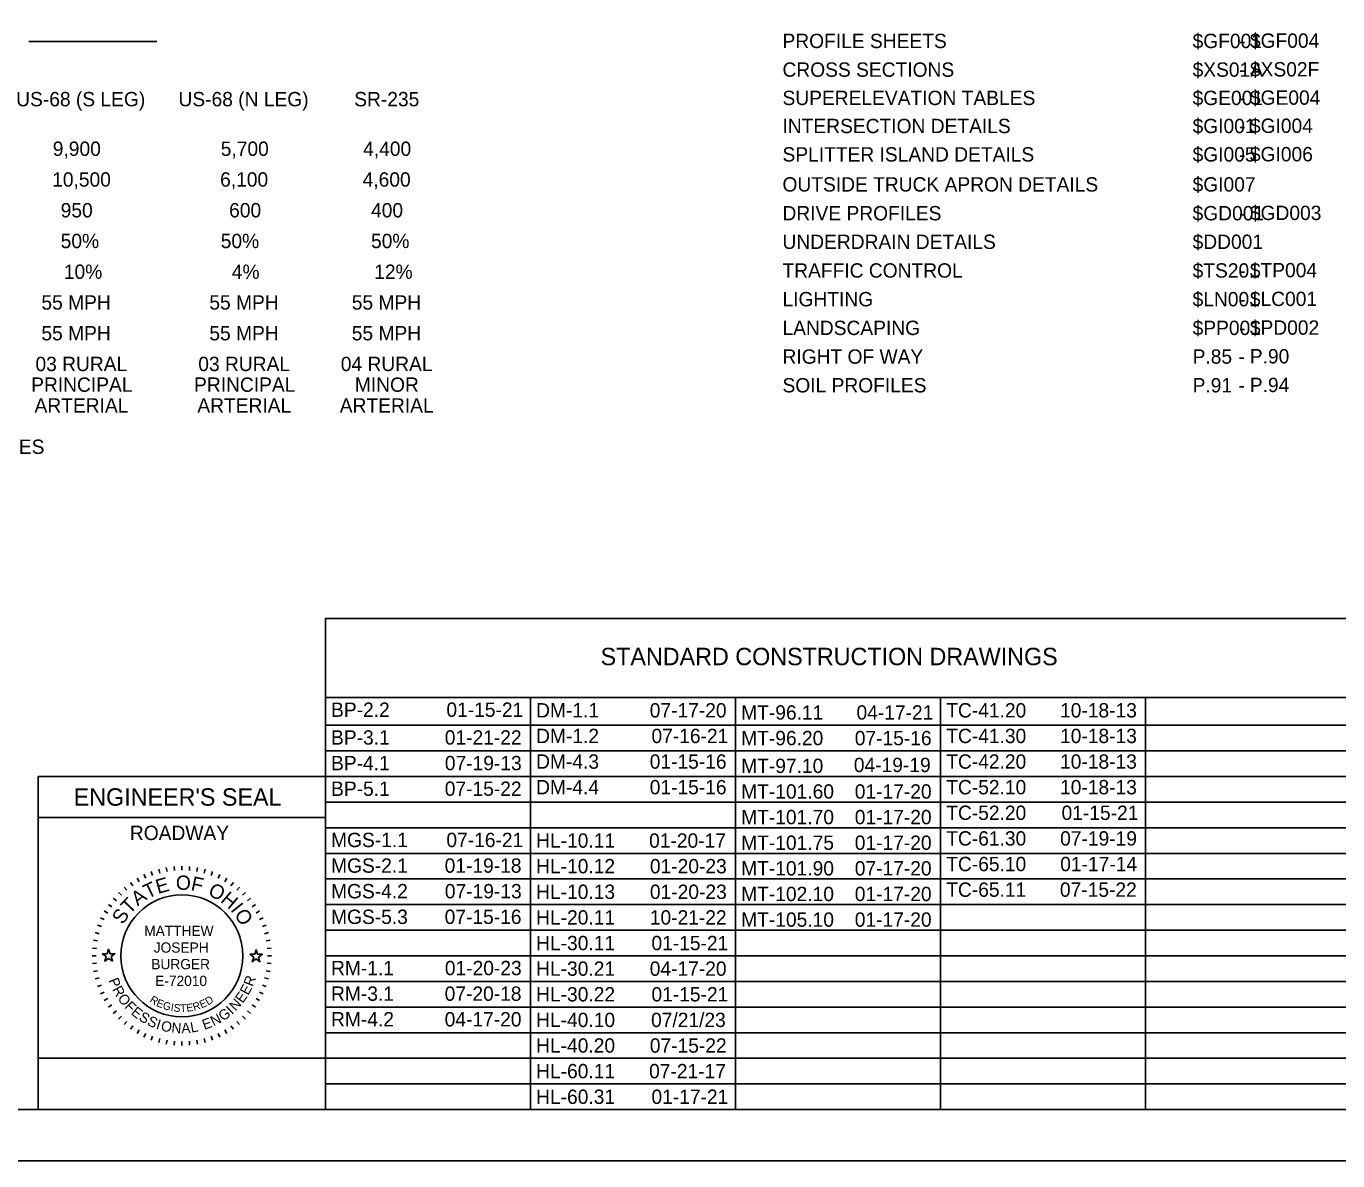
# Model space of a CAD drawing. Extents: x 39.5 to 73.5, y 15.6 to 37.6.
# Drawn here: x 47.83 to 60.62, y 15.6 to 26.67 of the extents above; entities that cross this region are included whole.
import ezdxf

# ---------------------------------------------------------------- set-up
doc = ezdxf.new("R2010")
doc.units = 0
for name, color, linetype in [('GM_X_City_Street', 7, 'Continuous'), ('GM_X_Hydro_Text', 7, 'Continuous'), ('GM_X_Interstate_Route', 7, 'Continuous'), ('GM_X_Major_River_Text', 7, 'Continuous')]:
    doc.layers.add(name, color=color, linetype=linetype)

msp = doc.modelspace()

# ---------------------------------------------------------------- linework, layer by layer
at = {"layer": 'GM_X_City_Street'}
msp.add_lwpolyline([(41.501, 37.101), (73.001, 37.101), (73.001, 16.101), (41.501, 16.101)], close=True, dxfattribs=at)
at = {"layer": 'GM_X_Hydro_Text'}
msp.add_lwpolyline([(39.501, 15.601), (73.501, 15.601), (73.501, 37.601), (39.501, 37.601)], close=True, dxfattribs=at)
at = {"layer": 'GM_X_Major_River_Text'}
for p, q in [((49.108, 26.523), (47.858, 26.523)), ((50.751, 20.893), (64.201, 20.893)), ((50.751, 16.101), (50.751, 20.893)), ((50.751, 20.122), (64.201, 20.122)), ((52.751, 16.101), (52.751, 20.122)), ((54.751, 16.101), (54.751, 20.122)), ((56.751, 16.101), (56.751, 20.122)), ((58.751, 16.101), (58.751, 20.122)), ((50.751, 19.851), (64.201, 19.851)), ((50.751, 19.601), (64.201, 19.601)), ((50.751, 19.351), (47.951, 19.351)), ((47.951, 19.351), (47.951, 16.101)), ((50.751, 19.351), (64.201, 19.351)), ((50.751, 16.101), (50.751, 19.351)), ((50.751, 19.101), (64.201, 19.101)), ((50.751, 18.951), (47.951, 18.951)), ((50.751, 18.851), (64.201, 18.851)), ((50.751, 18.601), (64.201, 18.601)), ((49.052, 18.423), (49.066, 18.386)), ((49.125, 18.446), (49.135, 18.408)), ((49.199, 18.463), (49.206, 18.423)), ((49.275, 18.473), (49.278, 18.433)), ((49.351, 18.476), (49.351, 18.436)), ((49.427, 18.473), (49.424, 18.433)), ((49.503, 18.463), (49.496, 18.423)), ((49.578, 18.446), (49.567, 18.408)), ((49.65, 18.423), (49.637, 18.386)), ((48.849, 18.318), (48.872, 18.285)), ((48.914, 18.359), (48.934, 18.324)), ((48.981, 18.394), (48.998, 18.358)), ((49.721, 18.394), (49.704, 18.358)), ((49.789, 18.359), (49.769, 18.324)), ((49.853, 18.318), (49.83, 18.285)), ((50.751, 18.351), (64.201, 18.351)), ((48.732, 18.22), (48.761, 18.192)), ((48.789, 18.271), (48.814, 18.241)), ((49.914, 18.271), (49.888, 18.241)), ((49.97, 18.22), (49.942, 18.192)), ((48.593, 18.039), (48.628, 18.019)), ((48.634, 18.103), (48.667, 18.08)), ((48.681, 18.164), (48.712, 18.138)), ((50.021, 18.164), (49.991, 18.138)), ((50.068, 18.103), (50.035, 18.08)), ((50.109, 18.039), (50.074, 18.019)), ((50.751, 18.101), (64.201, 18.101)), ((48.558, 17.971), (48.594, 17.954)), ((50.144, 17.971), (50.108, 17.954)), ((48.506, 17.828), (48.545, 17.817)), ((48.529, 17.9), (48.567, 17.887)), ((50.173, 17.9), (50.136, 17.887)), ((50.196, 17.828), (50.158, 17.817)), ((50.751, 17.851), (64.201, 17.851)), ((48.48, 17.677), (48.519, 17.674)), ((48.49, 17.753), (48.529, 17.746)), ((50.213, 17.753), (50.174, 17.746)), ((50.223, 17.677), (50.183, 17.674)), ((48.476, 17.601), (48.516, 17.601)), ((48.48, 17.525), (48.519, 17.528)), ((50.223, 17.525), (50.183, 17.528)), ((50.226, 17.601), (50.186, 17.601)), ((50.751, 17.601), (64.201, 17.601)), ((48.49, 17.449), (48.529, 17.456)), ((50.213, 17.449), (50.174, 17.456)), ((48.506, 17.375), (48.545, 17.385)), ((48.529, 17.302), (48.567, 17.315)), ((50.173, 17.302), (50.136, 17.315)), ((50.196, 17.375), (50.158, 17.385)), ((50.751, 17.351), (64.201, 17.351)), ((48.558, 17.231), (48.594, 17.248)), ((48.593, 17.164), (48.628, 17.184)), ((50.109, 17.164), (50.074, 17.184)), ((50.144, 17.231), (50.108, 17.248)), ((48.634, 17.099), (48.667, 17.122)), ((48.681, 17.039), (48.712, 17.064)), ((50.021, 17.039), (49.991, 17.064)), ((50.068, 17.099), (50.035, 17.122)), ((50.751, 17.101), (64.201, 17.101)), ((48.732, 16.982), (48.761, 17.011)), ((48.789, 16.931), (48.814, 16.961)), ((48.849, 16.884), (48.872, 16.917)), ((49.853, 16.884), (49.83, 16.917)), ((49.914, 16.931), (49.888, 16.961)), ((49.97, 16.982), (49.942, 17.011)), ((48.914, 16.843), (48.934, 16.878)), ((48.981, 16.808), (48.998, 16.844)), ((49.052, 16.779), (49.066, 16.816)), ((49.125, 16.756), (49.135, 16.795)), ((49.199, 16.739), (49.206, 16.779)), ((49.275, 16.729), (49.278, 16.769)), ((49.351, 16.726), (49.351, 16.766)), ((49.427, 16.729), (49.424, 16.769)), ((49.503, 16.739), (49.496, 16.779)), ((49.578, 16.756), (49.567, 16.795)), ((49.65, 16.779), (49.637, 16.816)), ((49.721, 16.808), (49.704, 16.844)), ((49.789, 16.843), (49.769, 16.878)), ((50.751, 16.851), (64.201, 16.851)), ((50.751, 16.601), (64.201, 16.601)), ((50.751, 16.351), (64.201, 16.351)), ((50.751, 16.101), (47.951, 16.101))]:
    msp.add_line(p, q, dxfattribs=at)
for points in [[(48.575, 17.621), (48.622, 17.621), (48.636, 17.666), (48.651, 17.621), (48.698, 17.621), (48.66, 17.593), (48.674, 17.549), (48.636, 17.576), (48.598, 17.549), (48.613, 17.593)], [(50.014, 17.616), (50.061, 17.616), (50.075, 17.66), (50.09, 17.616), (50.137, 17.616), (50.099, 17.588), (50.113, 17.543), (50.075, 17.571), (50.037, 17.543), (50.052, 17.588)], [(50.751, 16.101), (50.751, 16.601), (47.951, 16.601), (47.951, 16.101)]]:
    msp.add_lwpolyline(points, close=True, dxfattribs=at)
msp.add_circle((49.351, 17.601), 0.595, dxfattribs=at)

# ---------------------------------------------------------------- texts
at = {"layer": 'GM_X_Interstate_Route'}
for s, height, p in [('$GF001', 0.14, (59.209, 26.459)), ('$GF004', 0.14, (59.768, 26.462)), ('PROFILE SHEETS', 0.14, (55.209, 26.459)), ('-', 0.14, (59.664, 26.459)), ('CROSS SECTIONS', 0.14, (55.209, 26.179)), ('$XS01A', 0.14, (59.209, 26.179)), ('-', 0.14, (59.664, 26.179)), ('$XS02F', 0.14, (59.768, 26.182)), ('US-68 (S LEG)', 0.14, (47.735, 25.891)), ('US-68 (N LEG)', 0.14, (49.318, 25.891)), ('SR-235', 0.14, (51.032, 25.891)), ('SUPERELEVATION TABLES', 0.14, (55.209, 25.903)), ('$GE001', 0.14, (59.209, 25.903)), ('$GE004', 0.14, (59.768, 25.906)), ('-', 0.14, (59.664, 25.903)), ('INTERSECTION DETAILS', 0.14, (55.209, 25.629)), ('$GI001', 0.14, (59.209, 25.629)), ('$GI004', 0.14, (59.768, 25.631)), ('-', 0.14, (59.664, 25.629)), ('9,900', 0.14, (48.092, 25.407)), ('5,700', 0.14, (49.73, 25.407)), ('4,400', 0.14, (51.119, 25.407)), ('SPLITTER ISLAND DETAILS', 0.14, (55.209, 25.352)), ('$GI005', 0.14, (59.209, 25.352)), ('$GI006', 0.14, (59.768, 25.354)), ('-', 0.14, (59.664, 25.351)), ('10,500', 0.14, (48.086, 25.107)), ('6,100', 0.14, (49.724, 25.107)), ('4,600', 0.14, (51.114, 25.107)), ('OUTSIDE TRUCK APRON DETAILS', 0.14, (55.209, 25.059)), ('$GI007', 0.14, (59.209, 25.059)), ('950', 0.14, (48.169, 24.807)), ('600', 0.14, (49.812, 24.807)), ('400', 0.14, (51.196, 24.807)), ('DRIVE PROFILES', 0.14, (55.209, 24.778)), ('$GD001', 0.14, (59.209, 24.778)), ('-', 0.14, (59.664, 24.778)), ('$GD003', 0.14, (59.768, 24.781)), ('50%', 0.14, (48.169, 24.507)), ('50%', 0.14, (49.73, 24.507)), ('50%', 0.14, (51.196, 24.507)), ('UNDERDRAIN DETAILS', 0.14, (55.209, 24.499)), ('$DD001', 0.14, (59.209, 24.499)), ('10%', 0.14, (48.2, 24.207)), ('4%', 0.14, (49.838, 24.207)), ('12%', 0.14, (51.227, 24.207)), ('TRAFFIC CONTROL', 0.14, (55.209, 24.219)), ('$TS201', 0.14, (59.209, 24.219)), ('$TP004', 0.14, (59.767, 24.222)), ('-', 0.14, (59.664, 24.219)), ('LIGHTING ', 0.14, (55.209, 23.939)), ('$LN001', 0.14, (59.209, 23.939)), ('$LC001', 0.14, (59.767, 23.942)), ('55 MPH', 0.14, (47.981, 23.907)), ('55 MPH', 0.14, (49.619, 23.907)), ('55 MPH', 0.14, (51.008, 23.907)), ('-', 0.14, (59.664, 23.939)), ('LANDSCAPING', 0.14, (55.209, 23.659)), ('$PP001', 0.14, (59.209, 23.659)), ('$PD002', 0.14, (59.767, 23.662)), ('55 MPH', 0.14, (47.981, 23.607)), ('55 MPH', 0.14, (49.619, 23.607)), ('55 MPH', 0.14, (51.008, 23.607)), ('-', 0.14, (59.664, 23.659)), ('03 RURAL', 0.14, (47.923, 23.307)), ('03 RURAL', 0.14, (49.511, 23.307)), ('04 RURAL', 0.14, (50.901, 23.307)), ('RIGHT OF WAY', 0.14, (55.209, 23.379)), ('P.85', 0.14, (59.209, 23.379)), ('-', 0.14, (59.655, 23.379)), ('P.90', 0.14, (59.767, 23.382)), ('PRINCIPAL', 0.14, (47.881, 23.105)), ('PRINCIPAL', 0.14, (49.47, 23.105)), ('MINOR', 0.14, (51.038, 23.105)), ('SOIL PROFILES', 0.14, (55.209, 23.099)), ('P.91', 0.14, (59.209, 23.099)), ('-', 0.14, (59.655, 23.099)), ('P.94', 0.14, (59.767, 23.102)), ('ARTERIAL', 0.14, (47.914, 22.902)), ('ARTERIAL', 0.14, (49.502, 22.902)), ('ARTERIAL', 0.14, (50.891, 22.902)), ('NHS PROJECT.................................................................................YES', 0.14, (42.102, 22.499)), ('STANDARD CONSTRUCTION DRAWINGS', 0.17, (53.435, 20.437)), ('BP-2.2', 0.14, (50.806, 19.933)), ('01-15-21', 0.14, (51.931, 19.933)), ('DM-1.1', 0.14, (52.806, 19.927)), ('07-17-20', 0.14, (53.914, 19.927)), ('MT-96.11', 0.14, (54.806, 19.906)), ('04-17-21', 0.14, (55.931, 19.906)), ('TC-41.20', 0.14, (56.806, 19.927)), ('10-18-13', 0.14, (57.916, 19.927)), ('BP-3.1', 0.14, (50.806, 19.662)), ('01-21-22', 0.14, (51.915, 19.662)), ('DM-1.2', 0.14, (52.806, 19.677)), ('07-16-21', 0.14, (53.931, 19.677)), ('MT-96.20', 0.14, (54.806, 19.656)), ('07-15-16', 0.14, (55.914, 19.656)), ('TC-41.30', 0.14, (56.806, 19.677)), ('10-18-13', 0.14, (57.916, 19.677)), ('BP-4.1', 0.14, (50.806, 19.412)), ('07-19-13', 0.14, (51.916, 19.412)), ('DM-4.3', 0.14, (52.806, 19.427)), ('01-15-16', 0.14, (53.914, 19.427)), ('MT-97.10', 0.14, (54.806, 19.385)), ('04-19-19', 0.14, (55.905, 19.394)), ('TC-42.20', 0.14, (56.806, 19.427)), ('10-18-13', 0.14, (57.916, 19.427)), ('DM-4.4', 0.14, (52.806, 19.177)), ('01-15-16', 0.14, (53.914, 19.177)), ('TC-52.10', 0.14, (56.806, 19.177)), ('10-18-13', 0.14, (57.916, 19.177)), ('BP-5.1', 0.14, (50.806, 19.162)), ('07-15-22', 0.14, (51.915, 19.162)), ('MT-101.60', 0.14, (54.806, 19.135)), ('01-17-20', 0.14, (55.914, 19.135)), ('TC-52.20', 0.14, (56.806, 18.927)), ('01-15-21', 0.14, (57.931, 18.927)), ('MT-101.70', 0.14, (54.806, 18.885)), ('01-17-20', 0.14, (55.914, 18.885)), ('MGS-1.1', 0.14, (50.806, 18.662)), ('07-16-21', 0.14, (51.931, 18.662)), ('TC-61.30', 0.14, (56.806, 18.677)), ('07-19-19', 0.14, (57.917, 18.677)), ('HL-10.11', 0.14, (52.806, 18.656)), ('01-20-17', 0.14, (53.908, 18.656)), ('MT-101.75', 0.14, (54.806, 18.635)), ('01-17-20', 0.14, (55.914, 18.635)), ('MGS-2.1', 0.14, (50.806, 18.412)), ('01-19-18', 0.14, (51.914, 18.412)), ('TC-65.10', 0.14, (56.806, 18.427)), ('01-17-14', 0.14, (57.918, 18.427)), ('HL-10.12', 0.14, (52.806, 18.406)), ('01-20-23', 0.14, (53.916, 18.406)), ('MT-101.90', 0.14, (54.806, 18.385)), ('07-17-20', 0.14, (55.914, 18.385)), ('MGS-4.2', 0.14, (50.806, 18.162)), ('07-19-13', 0.14, (51.916, 18.162)), ('HL-10.13', 0.14, (52.806, 18.156)), ('01-20-23', 0.14, (53.916, 18.156)), ('TC-65.11', 0.14, (56.806, 18.177)), ('07-15-22', 0.14, (57.915, 18.177)), ('MT-102.10', 0.14, (54.806, 18.135)), ('01-17-20', 0.14, (55.914, 18.135)), ('MGS-5.3', 0.14, (50.806, 17.912)), ('07-15-16', 0.14, (51.914, 17.912)), ('HL-20.11', 0.14, (52.806, 17.906)), ('10-21-22', 0.14, (53.915, 17.906)), ('MT-105.10', 0.14, (54.806, 17.885)), ('01-17-20', 0.14, (55.914, 17.885)), ('HL-30.11', 0.14, (52.806, 17.656)), ('01-15-21', 0.14, (53.931, 17.656)), ('RM-1.1', 0.14, (50.806, 17.412)), ('01-20-23', 0.14, (51.916, 17.412)), ('HL-30.21', 0.14, (52.806, 17.406)), ('04-17-20', 0.14, (53.914, 17.406)), ('RM-3.1', 0.14, (50.806, 17.162)), ('07-20-18', 0.14, (51.914, 17.162)), ('HL-30.22', 0.14, (52.806, 17.156)), ('01-15-21', 0.14, (53.931, 17.156)), ('RM-4.2', 0.14, (50.806, 16.912)), ('04-17-20', 0.14, (51.914, 16.912)), ('HL-40.10', 0.14, (52.806, 16.906)), ('07/21/23', 0.14, (53.927, 16.906)), ('HL-40.20', 0.14, (52.806, 16.656)), ('07-15-22', 0.14, (53.915, 16.656)), ('HL-60.11', 0.14, (52.806, 16.406)), ('07-21-17', 0.14, (53.908, 16.406)), ('HL-60.31', 0.14, (52.806, 16.156)), ('01-17-21', 0.14, (53.931, 16.156))]:
    msp.add_text(s, height=height, dxfattribs=at).set_placement(p)
at = {"layer": 'GM_X_Major_River_Text'}
for s, height, p in [("ENGINEER'S SEAL", 0.17, (48.296, 19.066)), ('ROADWAY', 0.14, (48.844, 18.731)), ('MATTHEW ', 0.1, (48.984, 17.795)), ('JOSEPH', 0.1, (49.077, 17.632)), ('BURGER', 0.1, (49.053, 17.47)), ('E-72010', 0.1, (49.091, 17.307))]:
    msp.add_text(s, height=height, dxfattribs=at).set_placement(p)
for s, height, rotation, p in [('T', 0.14, 25.7167, (49.017, 18.155)), ('E', 0.14, 15.7571, (49.118, 18.204)), ('O', 0.14, 359.7812, (49.293, 18.245)), ('F', 0.14, 347.4362, (49.432, 18.243)), ('O', 0.14, 332.2586, (49.597, 18.199)), ('T', 0.14, 46.4344, (48.843, 18.001)), ('A', 0.14, 36.4747, (48.92, 18.083)), ('H', 0.14, 319.9136, (49.72, 18.133)), ('S', 0.14, 57.1924, (48.777, 17.899)), ('I', 0.14, 308.367, (49.819, 18.048)), ('O', 0.14, 303.1491, (49.857, 18.004)), ('R', 0.1, 69.2322, (50.042, 17.295)), ('P', 0.1, 291.494, (48.634, 17.363)), ('R', 0.1, 298.7311, (48.669, 17.274)), ('E', 0.1, 61.9951, (49.998, 17.21)), ('O', 0.1, 306.4666, (48.719, 17.186)), ('F', 0.1, 314.7068, (48.786, 17.099)), ('R', 0.075, 327.8239, (49.031, 17.155)), ('E', 0.075, 337.7777, (49.095, 17.114)), ('G', 0.075, 344.2727, (49.159, 17.086)), ('R', 0.075, 17.6836, (49.47, 17.064)), ('E', 0.075, 23.3052, (49.542, 17.087)), ('D', 0.075, 31.466, (49.606, 17.115)), ('N', 0.1, 47.0224, (49.875, 17.056)), ('E', 0.1, 54.758, (49.944, 17.132)), ('E', 0.1, 321.4393, (48.848, 17.036)), ('S', 0.1, 328.6764, (48.923, 16.978)), ('I', 0.075, 350.6464, (49.238, 17.064)), ('S', 0.075, 353.7858, (49.267, 17.059)), ('T', 0.075, 3.0061, (49.336, 17.052)), ('E', 0.075, 8.9826, (49.4, 17.054)), ('N', 0.1, 27.3113, (49.661, 16.911)), ('G', 0.1, 35.0469, (49.751, 16.959)), ('I', 0.1, 43.287, (49.839, 17.023)), ('S', 0.1, 335.9134, (49.005, 16.929)), ('I', 0.1, 343.1505, (49.093, 16.89)), ('O', 0.1, 346.8859, (49.14, 16.875)), ('N', 0.1, 355.1261, (49.246, 16.852)), ('A', 0.1, 2.8617, (49.348, 16.845)), ('L', 0.1, 10.0987, (49.443, 16.851)), ('E', 0.1, 20.0742, (49.571, 16.878))]:
    msp.add_text(s, height=height, rotation=rotation, dxfattribs=at).set_placement(p)

doc.saveas('drawing.dxf')
